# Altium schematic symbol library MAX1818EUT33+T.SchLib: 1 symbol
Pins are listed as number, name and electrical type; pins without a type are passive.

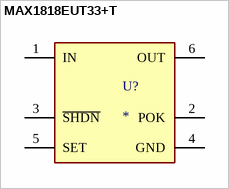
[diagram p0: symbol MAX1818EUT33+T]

## MAX1818EUT33+T
designator U?
Linear Voltage Regulator IC Positive Adjustable (Fixed) 1 Output 500mA SOT-23-6; MF: Maxim Integrated; MP: MAX1818EUT33+T
footprint SOT95P280X145-6N
pins: 1 IN, 2 POK, 3 ~{SHDN}, 4 GND, 5 SET, 6 OUT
